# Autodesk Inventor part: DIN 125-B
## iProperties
Shininess: 64.0
Length Units: 11269
Angle Units: 11279
Time Units: 11290
Mass Units: 11283
Length Display Precision: 3
Angle Display Precision: 2
Compacted: True
Created: 2002-08
Part Number: DIN 125-B
Material: 140 HV
Description: DIN 125-B / ISO 7090 - M18
Document SubType Name: Modeling
Designer: Cor de Vlaming
Density: 0.0
Volumn: 0.0
Area: 0.0
PropertySet Name: Model Information
Control State: 0
Master: False
Checked Out: False
Author: Cor de Vlaming
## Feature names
1. Extrusion2
2. Chamfer2
